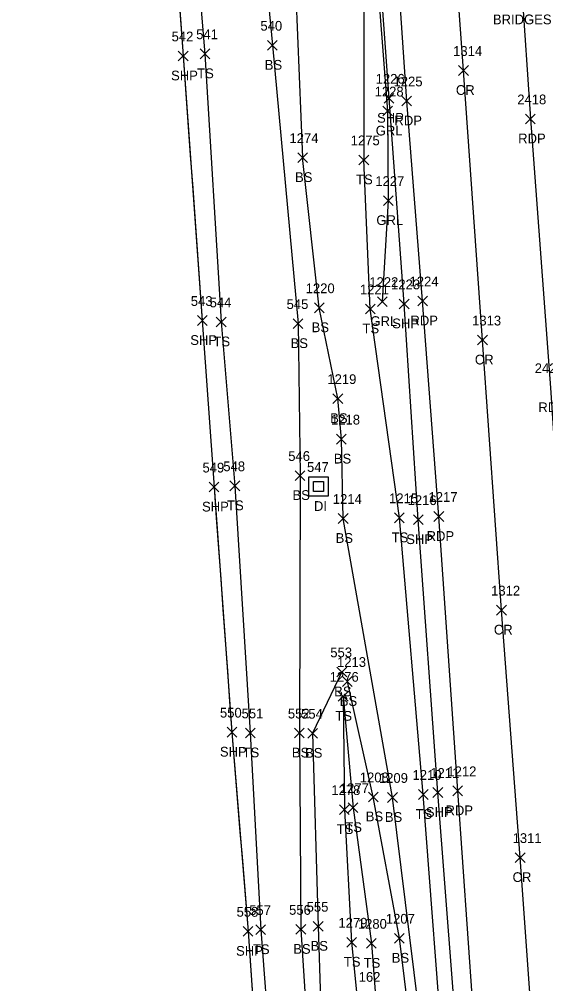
# Model space of a CAD drawing. Extents: x 1650221 to 1650634, y 244606 to 249996.
# Drawn here: x 1650231.8 to 1650339.8, y 246621.5 to 246819.2 of the extents above; entities that cross this region are included whole.
import ezdxf

# ---------------------------------------------------------------- set-up
doc = ezdxf.new("R2010")
doc.units = 0
for name, color, linetype in [('C_I', 7, 'Continuous'), ('D_A', 7, 'Continuous'), ('D_I', 7, 'Continuous'), ('DS', 7, 'Continuous'), ('L_A', 7, 'Continuous'), ('L_I', 7, 'Continuous'), ('L_TIC', 7, 'Continuous'), ('LELB', 7, 'Continuous'), ('LSOGP', 7, 'Continuous'), ('P_A', 7, 'Continuous'), ('P_I', 7, 'Continuous'), ('P_TIC', 7, 'Continuous'), ('PET', 7, 'Continuous'), ('PRC', 7, 'Continuous'), ('PSP', 7, 'Continuous'), ('R_A', 7, 'Continuous'), ('R_I', 7, 'Continuous'), ('R_TIC', 7, 'Continuous'), ('RGR', 7, 'Continuous'), ('S_C', 7, 'Continuous')]:
    doc.layers.add(name, color=color, linetype=linetype)

msp = doc.modelspace()

# ---------------------------------------------------------------- linework, layer by layer
at = {"layer": 'DS'}
for p, q in [((1650291.19, 246725.42), (1650295.19, 246725.42)), ((1650291.19, 246721.42), (1650291.19, 246725.42)), ((1650292.19, 246722.42), (1650292.19, 246724.42)), ((1650292.19, 246724.42), (1650294.19, 246724.42)), ((1650294.19, 246724.42), (1650294.19, 246722.42)), ((1650295.19, 246725.42), (1650295.19, 246721.42)), ((1650294.19, 246722.42), (1650292.19, 246722.42)), ((1650293.19, 246723.42), (1650293.19, 246723.42)), ((1650293.19, 246723.42), (1650293.19, 246723.42)), ((1650295.19, 246721.42), (1650291.19, 246721.42))]:
    msp.add_line(p, q, dxfattribs=at)
at = {"layer": 'L_TIC'}
for points in [[(1650268.89, 246811.16), (1650270.89, 246813.16)], [(1650270.89, 246811.16), (1650268.89, 246813.16)], [(1650282.73, 246812.9), (1650284.73, 246814.9)], [(1650284.73, 246812.9), (1650282.73, 246814.9)], [(1650288.93, 246789.87), (1650290.93, 246791.87)], [(1650290.93, 246789.87), (1650288.93, 246791.87)], [(1650288.93, 246789.87), (1650290.93, 246791.87)], [(1650290.93, 246789.87), (1650288.93, 246791.87)], [(1650301.49, 246789.4), (1650303.49, 246791.4)], [(1650303.49, 246789.4), (1650301.49, 246791.4)], [(1650301.49, 246789.4), (1650303.49, 246791.4)], [(1650303.49, 246789.4), (1650301.49, 246791.4)], [(1650292.34, 246759.07), (1650294.34, 246761.07)], [(1650294.34, 246759.07), (1650292.34, 246761.07)], [(1650302.8, 246758.84), (1650304.8, 246760.84)], [(1650304.8, 246758.84), (1650302.8, 246760.84)], [(1650272.23, 246756.17), (1650274.23, 246758.17)], [(1650274.23, 246756.17), (1650272.23, 246758.17)], [(1650288.01, 246755.82), (1650290.01, 246757.82)], [(1650290.01, 246755.82), (1650288.01, 246757.82)], [(1650296.15, 246740.44), (1650298.15, 246742.44)], [(1650298.15, 246740.44), (1650296.15, 246742.44)], [(1650296.89, 246732.14), (1650298.89, 246734.14)], [(1650298.89, 246732.14), (1650296.89, 246734.14)], [(1650288.41, 246724.67), (1650290.41, 246726.67)], [(1650290.41, 246724.67), (1650288.41, 246726.67)], [(1650275.03, 246722.56), (1650277.03, 246724.56)], [(1650277.03, 246722.56), (1650275.03, 246724.56)], [(1650297.25, 246715.86), (1650299.25, 246717.86)], [(1650299.25, 246715.86), (1650297.25, 246717.86)], [(1650308.78, 246716), (1650310.78, 246718)], [(1650310.78, 246716), (1650308.78, 246718)], [(1650296.97, 246684.4), (1650298.97, 246686.4)], [(1650298.97, 246684.4), (1650296.97, 246686.4)], [(1650298.11, 246682.43), (1650300.11, 246684.43)], [(1650300.11, 246682.43), (1650298.11, 246684.43)], [(1650297.24, 246679.39), (1650299.24, 246681.39)], [(1650299.24, 246679.39), (1650297.24, 246681.39)], [(1650297.24, 246679.39), (1650299.24, 246681.39)], [(1650299.24, 246679.39), (1650297.24, 246681.39)], [(1650278.21, 246671.89), (1650280.21, 246673.89)], [(1650280.21, 246671.89), (1650278.21, 246673.89)], [(1650288.28, 246671.86), (1650290.28, 246673.86)], [(1650290.28, 246671.86), (1650288.28, 246673.86)], [(1650290.99, 246671.81), (1650292.99, 246673.81)], [(1650292.99, 246671.81), (1650290.99, 246673.81)], [(1650303.43, 246658.77), (1650305.43, 246660.77)], [(1650305.43, 246658.77), (1650303.43, 246660.77)], [(1650307.36, 246658.65), (1650309.36, 246660.65)], [(1650309.36, 246658.65), (1650307.36, 246660.65)], [(1650313.68, 246659.27), (1650315.68, 246661.27)], [(1650315.68, 246659.27), (1650313.68, 246661.27)], [(1650297.51, 246656.16), (1650299.51, 246658.16)], [(1650299.51, 246656.16), (1650297.51, 246658.16)], [(1650299.27, 246656.56), (1650301.27, 246658.56)], [(1650301.27, 246656.56), (1650299.27, 246658.56)], [(1650280.34, 246631.54), (1650282.34, 246633.54)], [(1650282.34, 246631.54), (1650280.34, 246633.54)], [(1650288.57, 246631.6), (1650290.57, 246633.6)], [(1650290.57, 246631.6), (1650288.57, 246633.6)], [(1650292.12, 246632.23), (1650294.12, 246634.23)], [(1650294.12, 246632.23), (1650292.12, 246634.23)], [(1650308.77, 246629.78), (1650310.77, 246631.78)], [(1650310.77, 246629.78), (1650308.77, 246631.78)], [(1650298.98, 246628.97), (1650300.98, 246630.97)], [(1650300.98, 246628.97), (1650298.98, 246630.97)], [(1650303.04, 246628.74), (1650305.04, 246630.74)], [(1650305.04, 246628.74), (1650303.04, 246630.74)]]:
    msp.add_lwpolyline(points, dxfattribs=at)
at = {"layer": 'LELB'}
for points in [[(1650242.27, 247235.36), (1650241.91, 247206.66), (1650243.27, 247168.76), (1650246.51, 247128.17), (1650248.83, 247083.97), (1650252.85, 247030.65), (1650256.86, 246977.49), (1650260.95, 246918.52), (1650265.57, 246863.83), (1650269.89, 246812.16), (1650273.23, 246757.17), (1650276.03, 246723.56), (1650279.21, 246672.89), (1650281.34, 246632.54), (1650285.04, 246583.81), (1650287.41, 246538.25), (1650291.5, 246485.31), (1650295.53, 246435.79), (1650299.48, 246380.33), (1650302.27, 246339.43), (1650306.13, 246294.16), (1650309.79, 246242.03)], [(1650273.32, 247234.99), (1650275.56, 247178.37), (1650280.16, 247126.65), (1650283.32, 247073.18), (1650288.39, 247022.86), (1650291, 246971.3), (1650295.86, 246921.31), (1650299.12, 246867.86), (1650302.48, 246825.54), (1650302.49, 246790.4)], [(1650254.94, 247226.35), (1650251.19, 247207.91), (1650256.12, 247169.21), (1650259.77, 247133.43), (1650260.76, 247116.75), (1650264.32, 247083.63), (1650267.53, 247032.12), (1650271.47, 246976.78), (1650276.33, 246918.79), (1650279.06, 246862.8), (1650283.73, 246813.9), (1650289.01, 246756.82), (1650289.41, 246725.67), (1650289.28, 246672.86), (1650289.57, 246632.6), (1650292.55, 246585.88), (1650294.65, 246538.84), (1650297.54, 246482.61), (1650299.6, 246436.73), (1650304.05, 246378.94), (1650306.26, 246339.81), (1650313.05, 246293.73), (1650316.43, 246243)], [(1650258.46, 247225.14), (1650261.39, 247178.96), (1650264.81, 247125.04), (1650270.68, 247074.02), (1650274.2, 247020.9), (1650277.12, 246971.1), (1650282.14, 246919.24), (1650285.26, 246868.32), (1650288.53, 246824.34), (1650289.93, 246790.87)], [(1650334.26, 246221.72), (1650338.38, 246258.83), (1650337.59, 246300.3), (1650334.07, 246349), (1650333.58, 246369.4), (1650328.81, 246417.14), (1650325.98, 246458.24), (1650321.21, 246507.78), (1650319.29, 246555.26), (1650315.49, 246602.23), (1650308.36, 246659.65), (1650298.25, 246716.86), (1650297.89, 246733.14), (1650297.15, 246741.44), (1650293.34, 246760.07), (1650289.93, 246790.87)], [(1650347.02, 246221.82), (1650344.37, 246259.89), (1650340.76, 246300.88), (1650337.02, 246349.32), (1650337.24, 246369.2), (1650333.16, 246417.65), (1650330.19, 246458.39), (1650325.17, 246506.95), (1650322.34, 246555.74), (1650319.08, 246602.05), (1650314.68, 246660.27), (1650309.78, 246717), (1650303.8, 246759.84), (1650302.49, 246790.4)], [(1650297.97, 246685.4), (1650291.99, 246672.81), (1650293.12, 246633.23), (1650294.1, 246603.38)], [(1650330.33, 246258.11), (1650336.61, 246267.66), (1650335.63, 246300.25), (1650332.47, 246348.54), (1650331.57, 246369.5), (1650326.35, 246417.18), (1650323.43, 246458.49), (1650319.31, 246507.77), (1650317.45, 246555.33), (1650313.31, 246602.42), (1650309.77, 246630.78), (1650304.43, 246659.77), (1650299.11, 246683.43)], [(1650298.24, 246680.39), (1650300.27, 246657.56), (1650304.04, 246629.74), (1650305.72, 246608.28), (1650308.61, 246573.85), (1650309.06, 246546.86), (1650310.07, 246509.23), (1650312.74, 246470.67), (1650317.63, 246430.23), (1650317.82, 246407.13), (1650317.23, 246391.9), (1650323.59, 246373.12), (1650321.28, 246359.92), (1650319.29, 246343.11), (1650319.42, 246332.82)], [(1650298.24, 246680.39), (1650298.51, 246657.16), (1650299.98, 246629.97), (1650302.28, 246606.8), (1650303.3, 246573.46), (1650304.74, 246545.53), (1650305.21, 246510.64), (1650309.03, 246466.31), (1650311.77, 246430.96), (1650313.2, 246406.98), (1650311.23, 246390.61), (1650317.47, 246372.39), (1650313.3, 246358.43), (1650314.37, 246342.06), (1650319.42, 246332.82)]]:
    msp.add_lwpolyline(points, dxfattribs=at)
at = {"layer": 'LSOGP'}
msp.add_lwpolyline([(1650264.49, 246824.65), (1650264.96, 246818.18), (1650265.43, 246811.71), (1650265.92, 246804.93), (1650266.41, 246798.15), (1650266.9, 246791.36), (1650267.39, 246784.58), (1650267.89, 246777.8), (1650268.38, 246771.02), (1650268.87, 246764.24), (1650269.36, 246757.46), (1650269.96, 246748.92), (1650270.57, 246740.38), (1650271.17, 246731.84), (1650271.77, 246723.3), (1650272.23, 246717.02), (1650272.69, 246710.74), (1650273.14, 246704.46), (1650273.6, 246698.17), (1650274.06, 246691.89), (1650274.52, 246685.61), (1650274.97, 246679.33), (1650275.43, 246673.04), (1650275.85, 246667.94), (1650276.26, 246662.83), (1650276.68, 246657.73), (1650277.09, 246652.62), (1650277.51, 246647.51), (1650277.92, 246642.41), (1650278.34, 246637.3), (1650278.75, 246632.2), (1650279.17, 246626.2), (1650279.58, 246620.2)], dxfattribs=at)
at = {"layer": 'P_TIC'}
for points in [[(1650264.43, 246810.71), (1650266.43, 246812.71)], [(1650266.43, 246810.71), (1650264.43, 246812.71)], [(1650321.93, 246807.73), (1650323.93, 246809.73)], [(1650323.93, 246807.73), (1650321.93, 246809.73)], [(1650306.66, 246802.03), (1650308.66, 246804.03)], [(1650308.66, 246802.03), (1650306.66, 246804.03)], [(1650310.27, 246801.48), (1650312.27, 246803.48)], [(1650312.27, 246801.48), (1650310.27, 246803.48)], [(1650335.64, 246797.8), (1650337.64, 246799.8)], [(1650337.64, 246797.8), (1650335.64, 246799.8)], [(1650309.76, 246759.87), (1650311.76, 246761.87)], [(1650311.76, 246759.87), (1650309.76, 246761.87)], [(1650313.55, 246760.47), (1650315.55, 246762.47)], [(1650315.55, 246760.47), (1650313.55, 246762.47)], [(1650268.36, 246756.46), (1650270.36, 246758.46)], [(1650270.36, 246756.46), (1650268.36, 246758.46)], [(1650325.82, 246752.45), (1650327.82, 246754.45)], [(1650327.82, 246752.45), (1650325.82, 246754.45)], [(1650270.77, 246722.3), (1650272.77, 246724.3)], [(1650272.77, 246722.3), (1650270.77, 246724.3)], [(1650316.87, 246716.27), (1650318.87, 246718.27)], [(1650318.87, 246716.27), (1650316.87, 246718.27)], [(1650312.65, 246715.62), (1650314.65, 246717.62)], [(1650314.65, 246715.62), (1650312.65, 246717.62)], [(1650329.72, 246697.07), (1650331.72, 246699.07)], [(1650331.72, 246697.07), (1650329.72, 246699.07)], [(1650274.43, 246672.04), (1650276.43, 246674.04)], [(1650276.43, 246672.04), (1650274.43, 246674.04)], [(1650316.67, 246659.67), (1650318.67, 246661.67)], [(1650318.67, 246659.67), (1650316.67, 246661.67)], [(1650320.75, 246660.01), (1650322.75, 246662.01)], [(1650322.75, 246660.01), (1650320.75, 246662.01)], [(1650333.55, 246646.32), (1650335.55, 246648.32)], [(1650335.55, 246646.32), (1650333.55, 246648.32)], [(1650277.75, 246631.2), (1650279.75, 246633.2)], [(1650279.75, 246631.2), (1650277.75, 246633.2)]]:
    msp.add_lwpolyline(points, dxfattribs=at)
at = {"layer": 'PET'}
for points in [[(1650303.59, 247255.04), (1650306.81, 247216.14), (1650310.51, 247167.04), (1650313.87, 247117.51), (1650317.79, 247067.14), (1650321.46, 247013.25), (1650325.74, 246955.86), (1650329.2, 246907.19), (1650332.99, 246853.31), (1650336.64, 246798.8), (1650340.79, 246743.67), (1650343.55, 246701.32), (1650346.09, 246667.41)], [(1650353.63, 246221.52), (1650350.67, 246260.72), (1650347.78, 246301.59), (1650344.6, 246348.96), (1650342.99, 246369.43), (1650339.44, 246417.63), (1650336.53, 246459.1), (1650332.81, 246507), (1650329.1, 246556.8), (1650325.84, 246602.52), (1650321.75, 246661.01), (1650317.87, 246717.27), (1650314.55, 246761.47), (1650311.27, 246802.48), (1650308.51, 246843.59), (1650304.95, 246897.23), (1650300.96, 246950.35), (1650297.4, 247001.83), (1650293.63, 247056.22), (1650290.13, 247106.77), (1650285.97, 247166.23), (1650282.75, 247212.34), (1650279.98, 247248.95)]]:
    msp.add_lwpolyline(points, dxfattribs=at)
at = {"layer": 'PRC'}
msp.add_lwpolyline([(1650365.1, 246222.23), (1650362.04, 246265.67), (1650358.21, 246317.53), (1650354.88, 246368.98), (1650350.4, 246428.86), (1650346.57, 246483.13), (1650341.97, 246537.02), (1650338.57, 246591.04), (1650334.55, 246647.32), (1650330.72, 246698.07), (1650326.82, 246753.45), (1650322.93, 246808.73), (1650318.78, 246866.3), (1650315.63, 246915.25), (1650311.69, 246971.18), (1650308.09, 247021.19), (1650305.21, 247068.94), (1650301.6, 247120.36), (1650298.8, 247160.8), (1650294.82, 247207.2), (1650291.45, 247257.79)], dxfattribs=at)
at = {"layer": 'PSP'}
for points in [[(1650231.83, 247264.44), (1650236.38, 247206.75), (1650239.4, 247169.19), (1650242.51, 247127.54), (1650245.5, 247084.02), (1650249.81, 247030.22), (1650253.62, 246978.01), (1650257.98, 246918.58), (1650261.69, 246863.47), (1650265.43, 246811.71), (1650269.36, 246757.46), (1650271.77, 246723.3), (1650275.43, 246673.04), (1650278.75, 246632.2), (1650282.06, 246584.21), (1650285.45, 246538.51), (1650289.06, 246485.48), (1650292.63, 246435.74), (1650296.7, 246380.37), (1650299.48, 246339.42), (1650302.95, 246294.11), (1650306.82, 246242.11)], [(1650349.68, 246222.04), (1650346.67, 246260.34), (1650343.46, 246301.15), (1650340.56, 246349.22), (1650338.99, 246369.3), (1650335.68, 246417.66), (1650332.87, 246458.75), (1650329.36, 246506.58), (1650325.51, 246556.6), (1650322.14, 246602.26), (1650317.67, 246660.67), (1650313.65, 246716.62), (1650310.76, 246760.87), (1650307.66, 246803.03), (1650304.71, 246843.75), (1650300.95, 246897.67), (1650297.16, 246949.75), (1650293.72, 247001.93), (1650289.97, 247055.55), (1650286.03, 247107.65), (1650281.83, 247165.68), (1650278.51, 247212.85), (1650276.66, 247249.86)]]:
    msp.add_lwpolyline(points, dxfattribs=at)
at = {"layer": 'R_TIC'}
for points in [[(1650306.39, 246799.41), (1650308.39, 246801.41)], [(1650308.39, 246799.41), (1650306.39, 246801.41)], [(1650306.52, 246781.05), (1650308.52, 246783.05)], [(1650308.52, 246781.05), (1650306.52, 246783.05)], [(1650305.3, 246760.34), (1650307.3, 246762.34)], [(1650307.3, 246760.34), (1650305.3, 246762.34)]]:
    msp.add_lwpolyline(points, dxfattribs=at)
at = {"layer": 'RGR'}
msp.add_lwpolyline([(1650306.3, 246761.34), (1650307.52, 246782.05), (1650307.39, 246800.41), (1650304.06, 246843.7), (1650300.5, 246897.69), (1650296.68, 246949.72), (1650293.23, 247001.96), (1650289.46, 247055.48), (1650285.68, 247107.62), (1650281.2, 247166), (1650278.21, 247212.92), (1650276.32, 247247.97)], dxfattribs=at)

# ---------------------------------------------------------------- texts
at = {"layer": 'C_I'}
msp.add_text('162', height=2, dxfattribs=at).set_placement((1650301.43, 246621.86))
at = {"layer": 'D_A'}
msp.add_text('DI', height=2, dxfattribs=at).set_placement((1650292.25, 246718.42))
at = {"layer": 'D_I'}
msp.add_text('547', height=2, dxfattribs=at).set_placement((1650290.83, 246726.42))
at = {"layer": 'L_A'}
for s, p in [('TS', (1650268.3, 246807.16)), ('BS', (1650282.17, 246808.9)), ('BS', (1650288.38, 246785.87)), ('BS', (1650288.38, 246785.87)), ('TS', (1650300.9, 246785.4)), ('TS', (1650300.9, 246785.4)), ('BS', (1650291.78, 246755.07)), ('TS', (1650302.21, 246754.84)), ('TS', (1650271.64, 246752.17)), ('BS', (1650287.46, 246751.82)), ('BS', (1650295.59, 246736.44)), ('BS', (1650296.33, 246728.14)), ('BS', (1650287.85, 246720.67)), ('TS', (1650274.44, 246718.56)), ('BS', (1650296.7, 246711.86)), ('TS', (1650308.19, 246712)), ('BS', (1650296.41, 246680.4)), ('BS', (1650297.55, 246678.43)), ('TS', (1650296.65, 246675.39)), ('TS', (1650296.65, 246675.39)), ('TS', (1650277.62, 246667.89)), ('BS', (1650287.72, 246667.86)), ('BS', (1650290.43, 246667.81)), ('BS', (1650302.88, 246654.77)), ('TS', (1650313.09, 246655.27)), ('BS', (1650306.8, 246654.65)), ('TS', (1650296.92, 246652.16)), ('TS', (1650298.68, 246652.56)), ('TS', (1650279.75, 246627.54)), ('BS', (1650288.01, 246627.6)), ('BS', (1650291.56, 246628.23)), ('BS', (1650308.21, 246625.78)), ('TS', (1650298.39, 246624.97)), ('TS', (1650302.45, 246624.74))]:
    msp.add_text(s, height=2, dxfattribs=at).set_placement(p)
at = {"layer": 'L_I'}
for s, p in [('540', (1650281.28, 246816.9)), ('541', (1650268.1, 246815.16)), ('1274', (1650287.24, 246793.87)), ('1274', (1650287.24, 246793.87)), ('1275', (1650299.8, 246793.4)), ('1275', (1650299.8, 246793.4)), ('1220', (1650290.56, 246763.07)), ('1221', (1650301.68, 246762.84)), ('544', (1650270.87, 246760.17)), ('545', (1650286.65, 246759.82)), ('1219', (1650295.01, 246744.44)), ('1218', (1650295.76, 246736.14)), ('546', (1650286.99, 246728.67)), ('548', (1650273.67, 246726.56)), ('1215', (1650307.66, 246720)), ('1214', (1650296.13, 246719.86)), ('553', (1650295.61, 246688.4)), ('1213', (1650296.99, 246686.43)), ('1276', (1650295.49, 246683.39)), ('1276', (1650295.49, 246683.39)), ('551', (1650277.42, 246675.89)), ('552', (1650286.91, 246675.86)), ('554', (1650289.62, 246675.81)), ('1208', (1650301.66, 246662.77)), ('1209', (1650305.58, 246662.65)), ('1210', (1650312.47, 246663.27)), ('1278', (1650295.82, 246660.16)), ('1277', (1650297.57, 246660.56)), ('557', (1650278.98, 246635.54)), ('556', (1650287.16, 246635.6)), ('555', (1650290.76, 246636.23)), ('1279', (1650297.28, 246632.97)), ('1207', (1650307, 246633.78)), ('1280', (1650301.26, 246632.74))]:
    msp.add_text(s, height=2, dxfattribs=at).set_placement(p)
at = {"layer": 'P_A'}
for s, p in [('SHP', (1650262.96, 246806.71)), ('CR', (1650321.36, 246803.73)), ('SHP', (1650305.2, 246798.03)), ('RDP', (1650308.76, 246797.48)), ('RDP', (1650334.13, 246793.8)), ('SHP', (1650308.3, 246755.87)), ('RDP', (1650312.04, 246756.47)), ('SHP', (1650266.9, 246752.46)), ('CR', (1650325.25, 246748.45)), ('RDP', (1650338.28, 246738.67)), ('SHP', (1650269.31, 246718.3)), ('RDP', (1650315.36, 246712.27)), ('SHP', (1650311.19, 246711.62)), ('CR', (1650329.15, 246693.07)), ('SHP', (1650272.97, 246668.04)), ('SHP', (1650315.21, 246655.67)), ('RDP', (1650319.23, 246656.01)), ('CR', (1650332.98, 246642.32)), ('SHP', (1650276.29, 246627.2))]:
    msp.add_text(s, height=2, dxfattribs=at).set_placement(p)
at = {"layer": 'P_I'}
for s, p in [('542', (1650263.07, 246814.71)), ('1314', (1650320.8, 246811.73)), ('1226', (1650304.91, 246806.03)), ('1225', (1650308.58, 246805.48)), ('2418', (1650333.95, 246801.8)), ('1223', (1650308.07, 246763.87)), ('1224', (1650311.86, 246764.47)), ('543', (1650267, 246760.46)), ('1313', (1650324.69, 246756.45)), ('2423', (1650337.53, 246746.67)), ('549', (1650269.4, 246726.3)), ('1217', (1650315.75, 246720.27)), ('1216', (1650311.47, 246719.62)), ('1312', (1650328.59, 246701.07)), ('550', (1650272.98, 246676.04)), ('1211', (1650316.11, 246663.67)), ('1212', (1650319.62, 246664.01)), ('1311', (1650332.99, 246650.32)), ('558', (1650276.39, 246635.2))]:
    msp.add_text(s, height=2, dxfattribs=at).set_placement(p)
at = {"layer": 'R_A'}
for p in [(1650304.93, 246795.41), (1650305.06, 246777.05), (1650303.84, 246756.34)]:
    msp.add_text('GRL', height=2, dxfattribs=at).set_placement(p)
at = {"layer": 'R_I'}
for s, p in [('1228', (1650304.7, 246803.41)), ('1227', (1650304.83, 246785.05)), ('1222', (1650303.61, 246764.34))]:
    msp.add_text(s, height=2, dxfattribs=at).set_placement(p)
at = {"layer": 'S_C'}
msp.add_text('BRIDGES FREEZE BEFORE ROAD', height=2, dxfattribs=at).set_placement((1650328.95, 246818.21))

doc.saveas('drawing.dxf')
